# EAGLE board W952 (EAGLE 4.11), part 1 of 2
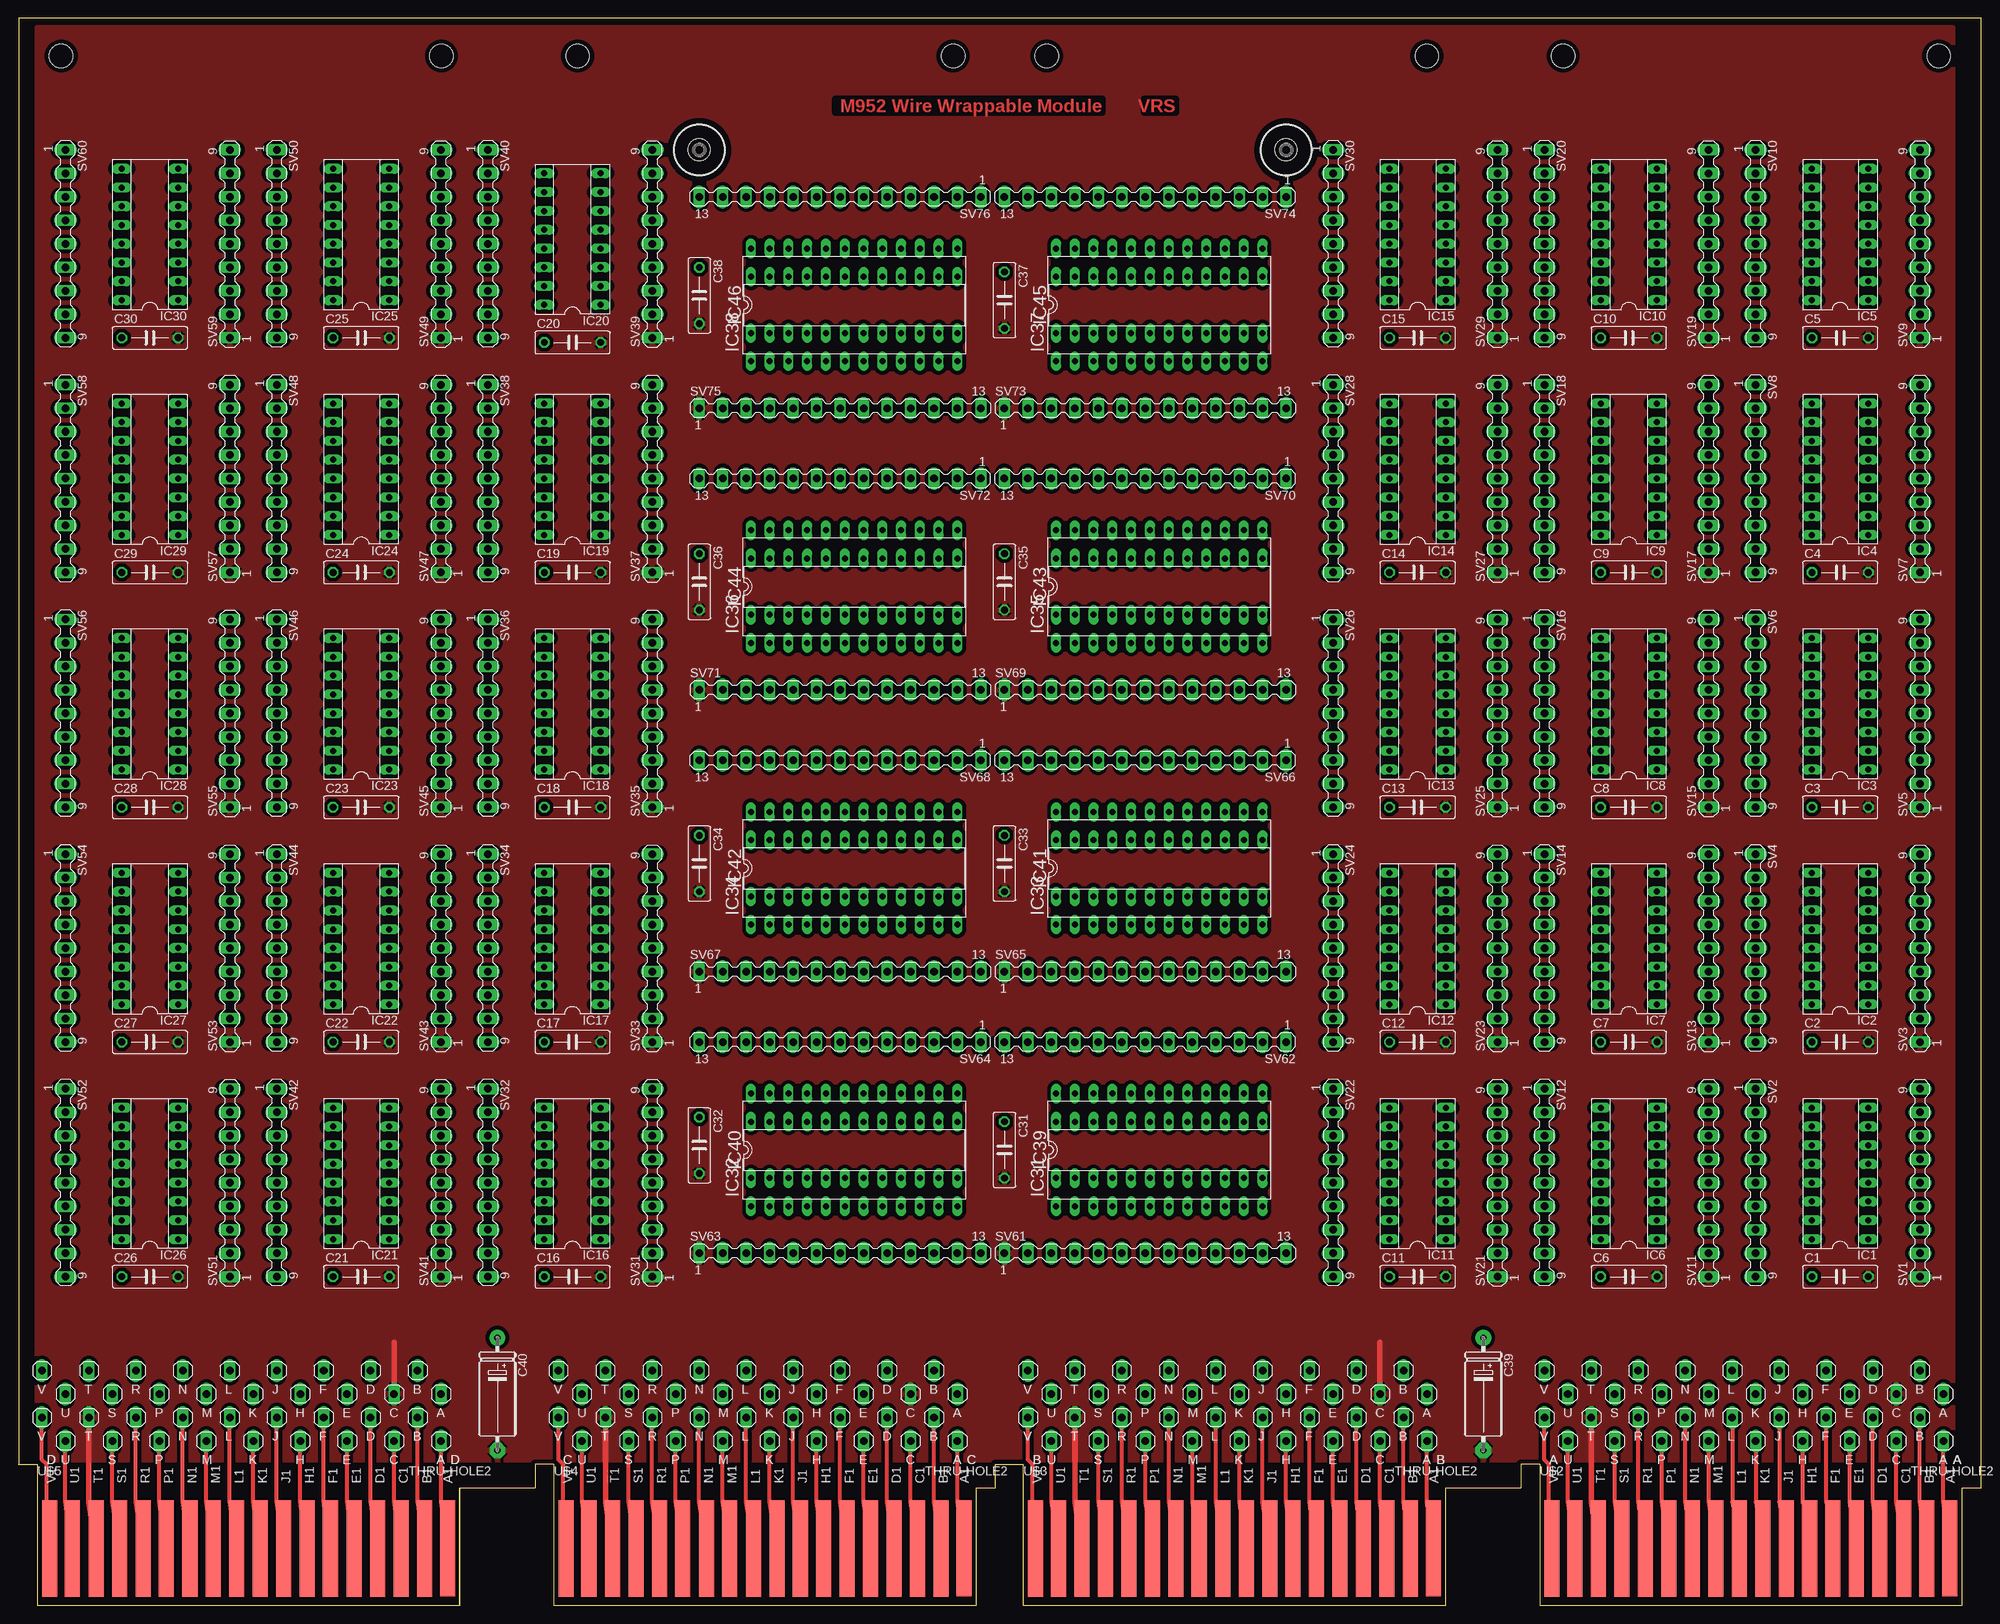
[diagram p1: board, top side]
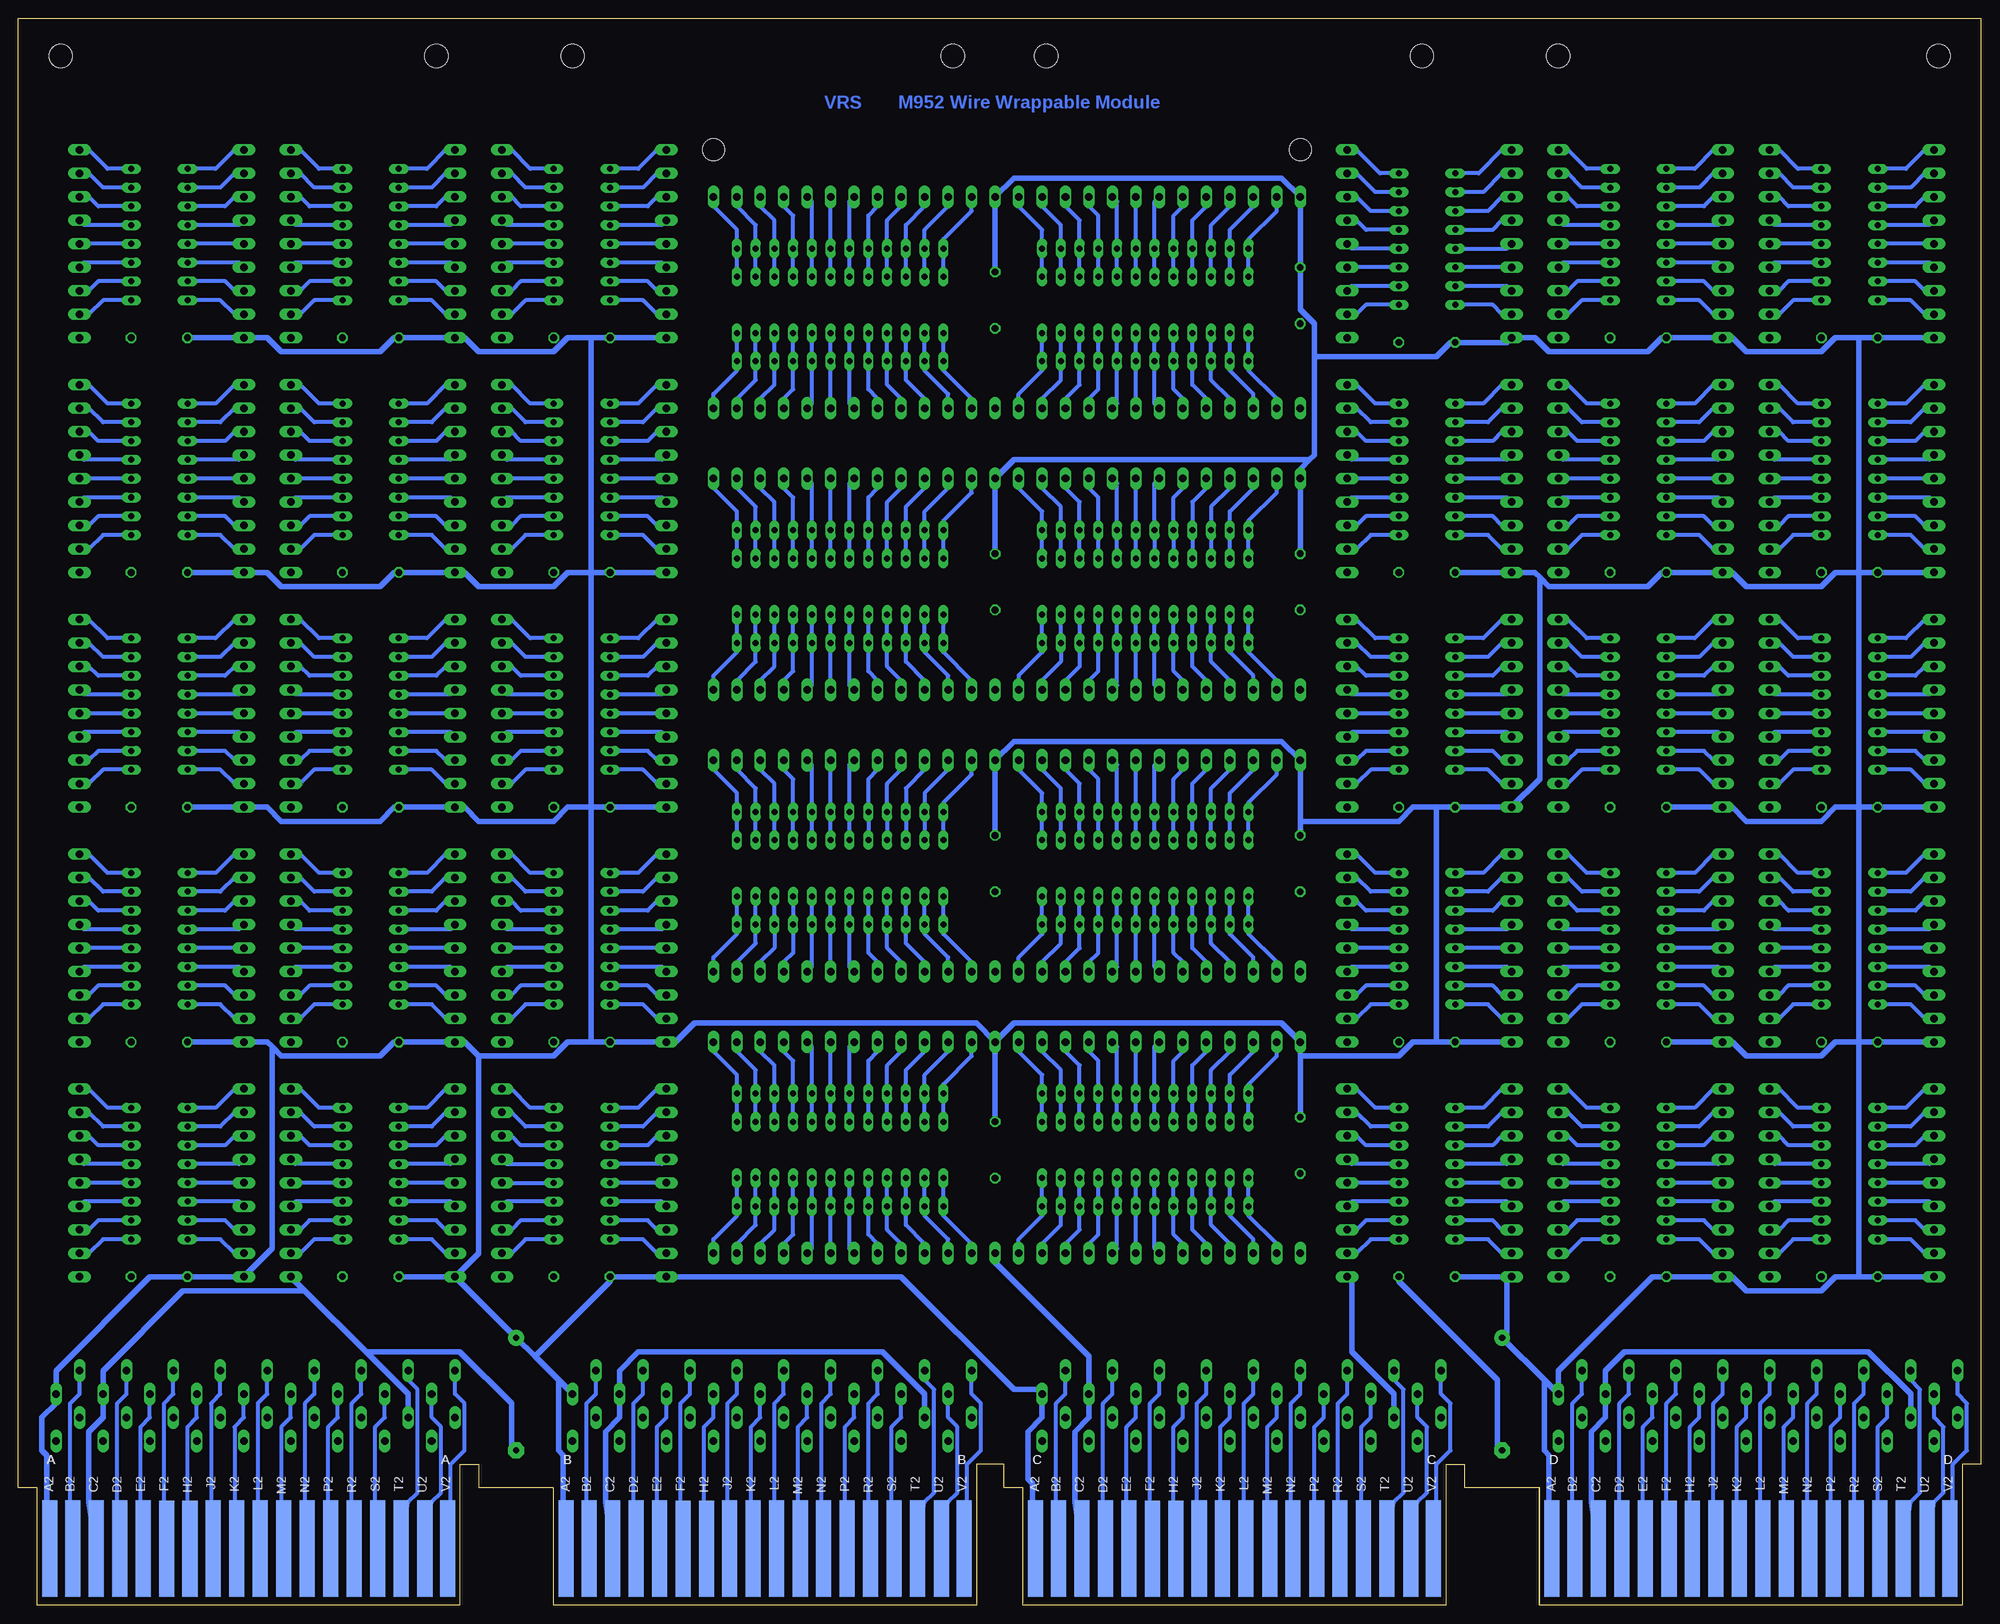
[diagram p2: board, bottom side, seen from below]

Size 265.43 x 214.63 mm. Coordinates in mm from the lower left corner, seen from the top.
Copper layers (1*16): Top 0.035mm / dielectric 1.5mm / Bottom 0.035mm
Design rules "olimex10mil": minimum track width 15mil, minimum drill 24mil, track to track 15mil, track to pad 10mil, pad to pad 10mil, via to via 10mil, smd to smd 10mil, copper to edge 25mil, drill to drill 10mil, minimum pad ring 10mil, minimum via ring 8mil, stop-mask expansion 0mil, vias tented up to drill 0mil, thermal gap 10mil
Net classes: 0 default: width 0.508 mm; 1 supply: width 0.762 mm

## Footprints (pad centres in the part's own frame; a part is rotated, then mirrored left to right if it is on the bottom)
C075-032X103 = drill 0.914 octagon: 1 -3.81,0; 2 3.81,0
E15-5 = drill 0.813 pad 2.159 round: + -7.62,0 | drill 0.813 pad 2.159 octagon: - 7.62,0
SOCKED-16 = drill 0.813 long: 1 -8.89,-3.81; 2 -6.35,-3.81; 3 -3.81,-3.81; 4 -1.27,-3.81; 5 1.27,-3.81; 6 3.81,-3.81; 7 6.35,-3.81; 8 8.89,-3.81; 9 8.89,3.81; 10 6.35,3.81; 11 3.81,3.81; 12 1.27,3.81; 13 -1.27,3.81; 14 -3.81,3.81; 15 -6.35,3.81; 16 -8.89,3.81
DIL24-6 = drill 0.813 long: 1 -13.97,-7.62; 2 -11.43,-7.62; 3 -8.89,-7.62; 4 -6.35,-7.62; 5 -3.81,-7.62; 6 -1.27,-7.62; 7 1.27,-7.62; 8 3.81,-7.62; 9 6.35,-7.62; 10 8.89,-7.62; 11 11.43,-7.62; 12 13.97,-7.62; 13 13.97,7.62; 14 11.43,7.62; 15 8.89,7.62; 16 6.35,7.62; 17 3.81,7.62; 18 1.27,7.62; 19 -1.27,7.62; 20 -3.81,7.62; 21 -6.35,7.62; 22 -8.89,7.62; 23 -11.43,7.62; 24 -13.97,7.62
DIL24-3 = drill 0.813 long: 1 -13.97,-3.81; 2 -11.43,-3.81; 3 -8.89,-3.81; 4 -6.35,-3.81; 5 -3.81,-3.81; 6 -1.27,-3.81; 7 1.27,-3.81; 8 3.81,-3.81; 9 6.35,-3.81; 10 8.89,-3.81; 11 11.43,-3.81; 12 13.97,-3.81; 13 13.97,3.81; 14 11.43,3.81; 15 8.89,3.81; 16 6.35,3.81; 17 3.81,3.81; 18 1.27,3.81; 19 -1.27,3.81; 20 -3.81,3.81; 21 -6.35,3.81; 22 -8.89,3.81; 23 -11.43,3.81; 24 -13.97,3.81
MA09-1 = drill 1.016 long: 1 -12.7,0; 2 -9.525,0; 3 -6.35,0; 4 -3.175,0; 5 0,0; 6 3.175,0; 7 6.35,0; 8 9.525,0; 9 12.7,0
MA13-1 = drill 1.016 long: 1 -19.05,0; 2 -15.875,0; 3 -12.7,0; 4 -9.525,0; 5 -6.35,0; 6 -3.175,0; 7 0,0; 8 3.175,0; 9 6.35,0; 10 9.525,0; 11 12.7,0; 12 15.875,0; 13 19.05,0
EDGE-CON8 = smd 2.032 x 13.017: AA1 261.223,7.709; AB1 258.118,7.684; AC1 254.956,7.684; AD1 251.765,7.684; AE1 248.59,7.693; AF1 245.389,7.668; AH1 242.24,7.668; AJ1 239.09,7.668; AK1 235.915,7.668; AL1 232.74,7.693; AM1 229.54,7.693; AN1 226.39,7.693; AP1 223.19,7.668; AR1 220.04,7.668; AS1 216.865,7.693; AT1 213.69,7.693; AU1 210.49,7.693; AV1 207.404,7.668; BA1 191.373,7.709; BB1 188.268,7.684; BC1 185.106,7.684; BD1 181.915,7.684; BE1 178.74,7.693; BF1 175.539,7.668; BH1 172.39,7.668; BJ1 169.24,7.668; BK1 166.065,7.668; BL1 162.89,7.693; BM1 159.69,7.693; BN1 156.54,7.693; BP1 153.34,7.668; BR1 150.19,7.668; BS1 147.015,7.693; BT1 143.84,7.693; BU1 140.64,7.693; BV1 137.554,7.668; CA1 127.873,7.709; CB1 124.768,7.684; CC1 121.606,7.684; CD1 118.415,7.684; CE1 115.24,7.693; CF1 112.039,7.668; CH1 108.89,7.668; CJ1 105.74,7.668; CK1 102.565,7.668; CL1 99.39,7.693; CM1 96.19,7.693; CN1 93.04,7.693; CP1 89.84,7.668; CR1 86.69,7.668; CS1 83.515,7.693; CT1 80.34,7.693; CU1 77.14,7.693; CV1 74.054,7.668; DA1 58.023,7.709; DB1 54.918,7.684; DC1 51.756,7.684; DD1 48.565,7.684; DE1 45.39,7.693; DF1 42.189,7.668; DH1 39.04,7.668; DJ1 35.89,7.668; DK1 32.715,7.668; DL1 29.54,7.693; DM1 26.34,7.693; DN1 23.19,7.693; DP1 19.99,7.668; DR1 16.84,7.668; DS1 13.665,7.693; DT1 10.49,7.693; DU1 7.29,7.693; DV1 4.204,7.668 | smd 2.032 x 13.017 bottom: AA2 261.223,7.69; AB2 258.102,7.668; AC2 254.94,7.668; AD2 251.765,7.693; AE2 248.59,7.693; AF2 245.389,7.642; AH2 242.24,7.642; AJ2 239.09,7.668; AK2 235.915,7.668; AL2 232.74,7.693; AM2 229.54,7.693; AN2 226.39,7.693; AP2 223.19,7.668; AR2 220.04,7.668; AS2 216.865,7.693; AT2 213.69,7.693; AU2 210.464,7.693; AV2 207.404,7.668; BA2 191.373,7.69; BB2 188.252,7.668; BC2 185.09,7.668; BD2 181.915,7.693; BE2 178.74,7.693; BF2 175.539,7.642; BH2 172.39,7.642; BJ2 169.24,7.668; BK2 166.065,7.668; BL2 162.89,7.693; BM2 159.69,7.693; BN2 156.54,7.693; BP2 153.34,7.668; BR2 150.19,7.668; BS2 147.015,7.693; BT2 143.84,7.693; BU2 140.614,7.693; BV2 137.554,7.668; CA2 127.873,7.69; CB2 124.752,7.668; CC2 121.59,7.668; CD2 118.415,7.693; CE2 115.24,7.693; CF2 112.039,7.642; CH2 108.89,7.642; CJ2 105.74,7.668; CK2 102.565,7.668; CL2 99.39,7.693; CM2 96.19,7.693; CN2 93.04,7.693; CP2 89.84,7.668; CR2 86.69,7.668; CS2 83.515,7.693; CT2 80.34,7.693; CU2 77.114,7.693; CV2 74.054,7.668; DA2 58.023,7.69; DB2 54.902,7.668; DC2 51.74,7.668; DD2 48.565,7.693; DE2 45.39,7.693; DF2 42.189,7.642; DH2 39.04,7.642; DJ2 35.89,7.668; DK2 32.715,7.668; DL2 29.54,7.693; DM2 26.34,7.693; DN2 23.19,7.693; DP2 19.99,7.668; DR2 16.84,7.668; DS2 13.665,7.693; DT2 10.49,7.693; DU2 7.264,7.693; DV2 4.204,7.668
THRU-HOLE2 = drill 1.016 long: A1 28.575,9.525; A2 28.575,3.175; B1 25.4,12.7; B2 25.4,6.35; C1 22.225,9.525; C2 22.225,3.175; D1 19.05,12.7; D2 19.05,6.35; E1 15.875,9.525; E2 15.875,3.175; F1 12.7,12.7; F2 12.7,6.35; H1 9.525,9.525; H2 9.525,3.175; J1 6.35,12.7; J2 6.35,6.35; K1 3.175,9.525; K2 3.175,3.175; L1 0,12.7; L2 0,6.35; M1 -3.175,9.525; M2 -3.175,3.175; N1 -6.35,12.7; N2 -6.35,6.35; P1 -9.525,9.525; P2 -9.525,3.175; R1 -12.7,12.7; R2 -12.7,6.35; S1 -15.875,9.525; S2 -15.875,3.175; T1 -19.05,12.7; T2 -19.05,6.35; U1 -22.225,9.525; U2 -22.225,3.175; V1 -25.4,12.7; V2 -25.4,6.35
OMNIBUS = hole 3.175: 208.915,209.55; 259.715,209.55; 190.5,209.55; 139.065,209.55; 75.616,209.55; 126.416,209.55; 57.201,209.55; 5.766,209.55
DRIL-3 = hole 3: 0,0

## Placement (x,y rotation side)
C1  [C075-032X103]  246.38,44.45 0 top
C2  [C075-032X103]  246.38,76.2 0 top
C3  [C075-032X103]  246.38,107.95 0 top
C4  [C075-032X103]  246.38,139.7 0 top
C5  [C075-032X103]  246.38,171.45 0 top
C6  [C075-032X103]  217.81,44.45 0 top
C7  [C075-032X103]  217.81,76.2 0 top
C8  [C075-032X103]  217.81,107.95 0 top
C9  [C075-032X103]  217.81,139.7 0 top
C10  [C075-032X103]  217.81,171.45 0 top
C11  [C075-032X103]  189.23,44.45 0 top
C12  [C075-032X103]  189.23,76.2 0 top
C13  [C075-032X103]  189.23,107.95 0 top
C14  [C075-032X103]  189.23,139.7 0 top
C15  [C075-032X103]  189.23,171.45 0 top
C16  [C075-032X103]  74.93,44.45 0 top
C17  [C075-032X103]  74.93,76.2 0 top
C18  [C075-032X103]  74.93,107.95 0 top
C19  [C075-032X103]  74.93,139.7 0 top
C20  [C075-032X103]  74.93,170.82 0 top
C21  [C075-032X103]  46.35,44.45 0 top
C22  [C075-032X103]  46.35,76.2 0 top
C23  [C075-032X103]  46.35,107.95 0 top
C24  [C075-032X103]  46.35,139.7 0 top
C25  [C075-032X103]  46.35,171.45 0 top
C26  [C075-032X103]  17.78,44.45 0 top
C27  [C075-032X103]  17.78,76.2 0 top
C28  [C075-032X103]  17.78,107.95 0 top
C29  [C075-032X103]  17.78,139.7 0 top
C30  [C075-032X103]  17.78,171.45 0 top
C31  [C075-032X103]  133.35,61.6 270 top
C32  [C075-032X103]  92.08,62.23 270 top
C33  [C075-032X103]  133.35,100.33 270 top
C34  [C075-032X103]  92.08,100.33 270 top
C35  [C075-032X103]  133.35,138.43 270 top
C36  [C075-032X103]  92.08,138.43 270 top
C37  [C075-032X103]  133.35,176.53 270 top
C38  [C075-032X103]  92.08,177.17 270 top
C39  [E15-5]  198.12,28.58 270 top
C40  [E15-5]  64.77,28.58 270 top
IC1  [SOCKED-16]  246.38,58.42 90 top
IC2  [SOCKED-16]  246.38,90.17 90 top
IC3  [SOCKED-16]  246.38,121.92 90 top
IC4  [SOCKED-16]  246.38,153.67 90 top
IC5  [SOCKED-16]  246.38,185.42 90 top
IC6  [SOCKED-16]  217.81,58.42 90 top
IC7  [SOCKED-16]  217.81,90.17 90 top
IC8  [SOCKED-16]  217.81,121.92 90 top
IC9  [SOCKED-16]  217.81,153.67 90 top
IC10  [SOCKED-16]  217.81,185.42 90 top
IC11  [SOCKED-16]  189.23,58.42 90 top
IC12  [SOCKED-16]  189.23,90.17 90 top
IC13  [SOCKED-16]  189.23,121.92 90 top
IC14  [SOCKED-16]  189.23,153.67 90 top
IC15  [SOCKED-16]  189.23,185.42 90 top
IC16  [SOCKED-16]  74.93,58.42 90 top
IC17  [SOCKED-16]  74.93,90.17 90 top
IC18  [SOCKED-16]  74.93,121.92 90 top
IC19  [SOCKED-16]  74.93,153.67 90 top
IC20  [SOCKED-16]  74.93,184.79 90 top
IC21  [SOCKED-16]  46.35,58.42 90 top
IC22  [SOCKED-16]  46.35,90.17 90 top
IC23  [SOCKED-16]  46.35,121.92 90 top
IC24  [SOCKED-16]  46.35,153.67 90 top
IC25  [SOCKED-16]  46.35,185.42 90 top
IC26  [SOCKED-16]  17.78,58.42 90 top
IC27  [SOCKED-16]  17.78,90.17 90 top
IC28  [SOCKED-16]  17.78,121.92 90 top
IC29  [SOCKED-16]  17.78,153.67 90 top
IC30  [SOCKED-16]  17.78,185.42 90 top
IC31  [DIL24-6]  154.31,61.6 0 top
IC32  [DIL24-6]  113.03,61.6 0 top
IC33  [DIL24-6]  154.31,99.7 0 top
IC34  [DIL24-6]  113.03,99.7 0 top
IC35  [DIL24-6]  154.31,137.8 0 top
IC36  [DIL24-6]  113.03,137.8 0 top
IC37  [DIL24-6]  154.31,175.9 0 top
IC38  [DIL24-6]  113.03,175.9 0 top
IC39  [DIL24-3]  154.31,61.6 0 top
IC40  [DIL24-3]  113.03,61.6 0 top
IC41  [DIL24-3]  154.31,99.7 0 top
IC42  [DIL24-3]  113.03,99.7 0 top
IC43  [DIL24-3]  154.31,137.8 0 top
IC44  [DIL24-3]  113.03,137.8 0 top
IC45  [DIL24-3]  154.31,175.9 0 top
IC46  [DIL24-3]  113.03,175.9 0 top
SV1  MA09-1  [MA09-1]  257.18,57.15 90 top
SV2  MA09-1  [MA09-1]  234.95,57.15 270 top
SV3  MA09-1  [MA09-1]  257.18,88.9 90 top
SV4  MA09-1  [MA09-1]  234.95,88.9 270 top
SV5  MA09-1  [MA09-1]  257.18,120.65 90 top
SV6  MA09-1  [MA09-1]  234.95,120.65 270 top
SV7  MA09-1  [MA09-1]  257.18,152.4 90 top
SV8  MA09-1  [MA09-1]  234.95,152.4 270 top
SV9  MA09-1  [MA09-1]  257.18,184.15 90 top
SV10  MA09-1  [MA09-1]  234.95,184.15 270 top
SV11  MA09-1  [MA09-1]  228.6,57.15 90 top
SV12  MA09-1  [MA09-1]  206.38,57.15 270 top
SV13  MA09-1  [MA09-1]  228.6,88.9 90 top
SV14  MA09-1  [MA09-1]  206.38,88.9 270 top
SV15  MA09-1  [MA09-1]  228.6,120.65 90 top
SV16  MA09-1  [MA09-1]  206.38,120.65 270 top
SV17  MA09-1  [MA09-1]  228.6,152.4 90 top
SV18  MA09-1  [MA09-1]  206.38,152.4 270 top
SV19  MA09-1  [MA09-1]  228.6,184.15 90 top
SV20  MA09-1  [MA09-1]  206.38,184.15 270 top
SV21  MA09-1  [MA09-1]  200.03,57.15 90 top
SV22  MA09-1  [MA09-1]  177.8,57.15 270 top
SV23  MA09-1  [MA09-1]  200.03,88.9 90 top
SV24  MA09-1  [MA09-1]  177.8,88.9 270 top
SV25  MA09-1  [MA09-1]  200.03,120.65 90 top
SV26  MA09-1  [MA09-1]  177.8,120.65 270 top
SV27  MA09-1  [MA09-1]  200.03,152.4 90 top
SV28  MA09-1  [MA09-1]  177.8,152.4 270 top
SV29  MA09-1  [MA09-1]  200.03,184.15 90 top
SV30  MA09-1  [MA09-1]  177.8,184.15 270 top
SV31  MA09-1  [MA09-1]  85.72,57.15 90 top
SV32  MA09-1  [MA09-1]  63.5,57.15 270 top
SV33  MA09-1  [MA09-1]  85.72,88.9 90 top
SV34  MA09-1  [MA09-1]  63.5,88.9 270 top
SV35  MA09-1  [MA09-1]  85.72,120.65 90 top
SV36  MA09-1  [MA09-1]  63.5,120.65 270 top
SV37  MA09-1  [MA09-1]  85.72,152.4 90 top
SV38  MA09-1  [MA09-1]  63.5,152.4 270 top
SV39  MA09-1  [MA09-1]  85.72,184.15 90 top
SV40  MA09-1  [MA09-1]  63.5,184.15 270 top
SV41  MA09-1  [MA09-1]  57.15,57.15 90 top
SV42  MA09-1  [MA09-1]  34.92,57.15 270 top
SV43  MA09-1  [MA09-1]  57.15,88.9 90 top
SV44  MA09-1  [MA09-1]  34.92,88.9 270 top
SV45  MA09-1  [MA09-1]  57.15,120.65 90 top
SV46  MA09-1  [MA09-1]  34.92,120.65 270 top
SV47  MA09-1  [MA09-1]  57.15,152.4 90 top
SV48  MA09-1  [MA09-1]  34.92,152.4 270 top
SV49  MA09-1  [MA09-1]  57.15,184.15 90 top
SV50  MA09-1  [MA09-1]  34.92,184.15 270 top
SV51  MA09-1  [MA09-1]  28.57,57.15 90 top
SV52  MA09-1  [MA09-1]  6.35,57.15 270 top
SV53  MA09-1  [MA09-1]  28.57,88.9 90 top
SV54  MA09-1  [MA09-1]  6.35,88.9 270 top
SV55  MA09-1  [MA09-1]  28.57,120.65 90 top
SV56  MA09-1  [MA09-1]  6.35,120.65 270 top
SV57  MA09-1  [MA09-1]  28.57,152.4 90 top
SV58  MA09-1  [MA09-1]  6.35,152.4 270 top
SV59  MA09-1  [MA09-1]  28.57,184.15 90 top
SV60  MA09-1  [MA09-1]  6.35,184.15 270 top
SV61  MA13-1  [MA13-1]  152.4,47.63 0 top
SV62  MA13-1  [MA13-1]  152.4,76.2 180 top
SV63  MA13-1  [MA13-1]  111.12,47.63 0 top
SV64  MA13-1  [MA13-1]  111.12,76.2 180 top
SV65  MA13-1  [MA13-1]  152.4,85.73 0 top
SV66  MA13-1  [MA13-1]  152.4,114.3 180 top
SV67  MA13-1  [MA13-1]  111.12,85.73 0 top
SV68  MA13-1  [MA13-1]  111.12,114.3 180 top
SV69  MA13-1  [MA13-1]  152.4,123.83 0 top
SV70  MA13-1  [MA13-1]  152.4,152.4 180 top
SV71  MA13-1  [MA13-1]  111.12,123.83 0 top
SV72  MA13-1  [MA13-1]  111.12,152.4 180 top
SV73  MA13-1  [MA13-1]  152.4,161.93 0 top
SV74  MA13-1  [MA13-1]  152.4,190.5 180 top
SV75  MA13-1  [MA13-1]  111.12,161.93 0 top
SV76  MA13-1  [MA13-1]  111.12,190.5 180 top
U$1  [EDGE-CON8]  0,0 0 top
U$2  THRU-HOLE2  [THRU-HOLE2]  231.78,19.05 0 top
U$3  THRU-HOLE2  [THRU-HOLE2]  161.93,19.05 0 top
U$4  THRU-HOLE2  [THRU-HOLE2]  98.42,19.05 0 top
U$5  THRU-HOLE2  [THRU-HOLE2]  28.57,19.05 0 top
U$8  OUTLINE-OMNIBUS  [OMNIBUS]  0,0 0 top
U$9  [DRIL-3]  92.08,196.85 0 top
U$10  [DRIL-3]  171.45,196.85 0 top

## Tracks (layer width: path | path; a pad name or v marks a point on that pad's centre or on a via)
GND
  Top 0.762: U$3.T2 142.88,13.97 U$1.BT1 | U$5.T2 9.53,13.97 U$1.DT1 | U$1.CT1 79.38,13.97 U$4.T2 | U$1.AT1 212.72,13.97 U$2.T2 | U$5.C1 50.8,35.56 | U$3.C1 184.15,35.56
  Bottom 0.762: U$1.BC2 186.06,13.97 186.06,23.5 184.15,25.4 U$3.C1 184.15,31.75 181.61,34.29 148.59,34.29 142.88,28.58 U$3.T2 | U$1.DC2 52.7,13.97 52.7,23.5 50.8,25.4 U$5.C1 50.8,31.75 48.26,34.29 15.24,34.29 9.53,28.58 U$5.T2 | U$1.AC2 255.91,13.97 255.91,23.5 254,25.4 U$2.C1 254,31.75 243.21,42.55 226.69,42.55 | U$1.CC2 122.56,13.97 122.56,23.5 120.65,25.4 U$4.C1 120.65,33.66 133.35,46.36 SV61.1 | U$4.T2 79.38,28.58 85.09,34.29 85.09,43.82 SV31.1 | 226.69,42.55 218.44,34.29 | 218.44,34.29 212.72,28.58 U$2.T2 | 226.69,42.55 SV11.1 | C40.- 65.41,21.59 65.41,30.48 78.74,43.82 C16.2 | 218.44,34.29 205.74,34.29 198.75,27.31 198.75,21.59 C39.-
  pour Top (isolate 0.508): 2.54,19.69 261.62,19.69 261.62,213.36 2.54,213.36
N$1
  Top 0.508: U$2.K2 234.95,13.97 U$1.AK1
N$2
  Top 0.508: U$2.J2 238.12,13.97 U$1.AJ1
N$3
  Top 0.508: U$2.H2 241.3,13.97 U$1.AH1
N$4
  Top 0.508: U$2.L2 231.78,13.97 U$1.AL1
N$5
  Top 0.508: U$2.M2 228.6,13.97 U$1.AM1
N$6
  Top 0.508: U$2.N2 225.43,13.97 U$1.AN1
N$7
  Top 0.508: U$2.P2 222.25,13.97 U$1.AP1
N$8
  Top 0.508: U$2.F2 244.47,13.97 U$1.AF1
N$9
  Top 0.508: U$2.E2 247.65,13.97 U$1.AE1
N$10
  Top 0.508: U$2.D2 250.82,13.97 U$1.AD1
N$11
  Top 0.508: U$2.C2 254,13.97 U$1.AC1
N$12
  Top 0.508: U$2.R2 219.07,13.97 U$1.AR1
N$13
  Top 0.508: U$2.S2 215.9,13.97 U$1.AS1
N$14
  Top 0.508: U$2.B2 257.18,13.97 U$1.AB1
N$15
  Top 0.508: U$2.A2 260.35,13.97 U$1.AA1
N$16
  Top 0.508: U$2.U2 209.55,13.97 U$1.AU1
N$17
  Top 0.508: U$2.V2 206.38,19.69 207.01,19.05 207.01,13.97 U$1.AV1
N$18
  Bottom 0.508: U$2.V1 206.38,28.58 205.1,27.31 205.1,20.96 207.01,19.05 207.01,13.97 U$1.AV2
N$19
  Bottom 0.508: U$2.U1 209.55,25.4 208.28,24.13 208.28,15.24 209.55,13.97 U$1.AU2
N$20
  Bottom 0.508: U$2.T1 212.72,30.48 211.46,29.21 211.46,15.24 212.72,13.97 U$1.AT2
N$21
  Bottom 0.508: U$2.S1 215.9,25.4 217.17,24.13 217.17,13.97 U$1.AS2
N$22
  Bottom 0.508: U$2.R1 219.07,28.58 220.34,27.31 220.34,13.97 U$1.AR2
N$23
  Bottom 0.508: U$2.P1 222.25,25.4 223.52,24.13 223.52,13.97 U$1.AP2
N$24
  Bottom 0.508: U$2.N1 225.43,28.58 226.69,27.31 226.69,13.97 U$1.AN2
N$25
  Bottom 0.508: U$2.M1 228.6,25.4 229.87,24.13 229.87,13.97 U$1.AM2
N$26
  Bottom 0.508: U$2.L1 231.78,28.58 233.04,27.31 233.04,13.97 U$1.AL2
N$27
  Bottom 0.508: U$2.K1 234.95,25.4 236.22,24.13 236.22,13.97 U$1.AK2
N$28
  Bottom 0.508: U$2.J1 238.12,28.58 239.4,27.31 239.4,13.97 U$1.AJ2
N$29
  Bottom 0.508: U$2.H1 241.3,25.4 242.57,24.13 242.57,13.97 U$1.AH2
N$30
  Bottom 0.508: U$2.F1 244.47,28.58 245.75,27.31 245.75,13.97 U$1.AF2
N$31
  Bottom 0.508: U$2.E1 247.65,25.4 248.92,24.13 248.92,13.97 U$1.AE2
N$32
  Bottom 0.508: U$2.D1 250.82,28.58 252.09,27.31 252.09,13.97 U$1.AD2
N$33
  Bottom 0.508: U$2.B1 257.18,28.58 258.44,27.31 258.44,13.97 U$1.AB2
N$34
  Top 0.508: U$3.V2 136.53,19.69 137.16,19.05 137.16,13.97 U$1.BV1
N$35
  Top 0.508: U$3.U2 139.7,13.97 U$1.BU1
N$36
  Top 0.508: U$3.S2 146.05,13.97 U$1.BS1
N$37
  Top 0.508: U$3.R2 149.22,13.97 U$1.BR1
N$38
  Top 0.508: U$3.P2 152.4,13.97 U$1.BP1
N$39
  Top 0.508: U$3.N2 155.57,13.97 U$1.BN1
N$40
  Top 0.508: U$3.M2 158.75,13.97 U$1.BM1
N$41
  Top 0.508: U$3.L2 161.93,13.97 U$1.BL1
N$42
  Top 0.508: U$3.K2 165.1,13.97 U$1.BK1
N$43
  Top 0.508: U$3.J2 168.28,13.97 U$1.BJ1
N$44
  Top 0.508: U$3.H2 171.45,13.97 U$1.BH1
N$45
  Top 0.508: U$3.F2 174.62,13.97 U$1.BF1
N$46
  Top 0.508: U$3.E2 177.8,13.97 U$1.BE1
N$47
  Top 0.508: U$3.D2 180.97,13.97 U$1.BD1
N$48
  Top 0.508: U$3.C2 184.15,13.97 U$1.BC1
N$49
  Top 0.508: U$3.B2 187.32,13.97 U$1.BB1
N$50
  Top 0.508: U$3.A2 190.5,13.97 U$1.BA1
N$51
  Bottom 0.508: U$3.V1 136.53,28.58 135.25,27.31 135.25,20.96 137.16,19.05 137.16,13.97 U$1.BV2
N$52
  Bottom 0.508: U$3.U1 139.7,25.4 138.43,24.13 138.43,15.24 139.7,13.97 U$1.BU2
N$53
  Bottom 0.508: U$3.T1 142.88,30.48 141.6,29.21 141.6,15.24 142.88,13.97 U$1.BT2
N$54
  Bottom 0.508: U$3.S1 146.05,25.4 147.32,24.13 147.32,13.97 U$1.BS2
N$55
  Bottom 0.508: U$3.R1 149.22,28.58 150.5,27.31 150.5,13.97 U$1.BR2
N$56
  Bottom 0.508: U$3.P1 152.4,25.4 153.67,24.13 153.67,13.97 U$1.BP2
N$57
  Bottom 0.508: U$3.N1 155.57,28.58 156.84,27.31 156.84,13.97 U$1.BN2
N$58
  Bottom 0.508: U$3.M1 158.75,25.4 160.02,24.13 160.02,13.97 U$1.BM2
N$59
  Bottom 0.508: U$3.L1 161.93,28.58 163.19,27.31 163.19,13.97 U$1.BL2
N$60
  Bottom 0.508: U$3.K1 165.1,25.4 166.37,24.13 166.37,13.97 U$1.BK2
N$61
  Bottom 0.508: U$3.J1 168.28,28.58 169.54,27.31 169.54,13.97 U$1.BJ2
N$62
  Bottom 0.508: U$3.H1 171.45,25.4 172.72,24.13 172.72,13.97 U$1.BH2
N$63
  Bottom 0.508: U$3.F1 174.62,28.58 175.9,27.31 175.9,13.97 U$1.BF2
N$64
  Bottom 0.508: U$3.E1 177.8,25.4 179.07,24.13 179.07,13.97 U$1.BE2
N$65
  Bottom 0.508: U$3.D1 180.97,28.58 182.25,27.31 182.25,13.97 U$1.BD2
N$66
  Bottom 0.508: U$3.B1 187.32,28.58 188.59,27.31 188.59,13.97 U$1.BB2
N$67
  Top 0.508: U$4.V2 73.03,19.69 73.66,19.05 73.66,13.97 U$1.CV1
N$68
  Top 0.508: U$4.U2 76.2,13.97 U$1.CU1
N$69
  Top 0.508: U$4.S2 82.55,13.97 U$1.CS1
N$70
  Top 0.508: U$4.R2 85.72,13.97 U$1.CR1
N$71
  Top 0.508: U$4.P2 88.9,13.97 U$1.CP1
N$72
  Top 0.508: U$4.N2 92.08,13.97 U$1.CN1
N$73
  Top 0.508: U$4.M2 95.25,13.97 U$1.CM1
N$74
  Top 0.508: U$4.L2 98.42,13.97 U$1.CL1
N$75
  Top 0.508: U$4.K2 101.6,13.97 U$1.CK1
N$76
  Top 0.508: U$4.J2 104.78,13.97 U$1.CJ1
N$77
  Top 0.508: U$4.H2 107.95,13.97 U$1.CH1
N$78
  Top 0.508: U$4.F2 111.12,13.97 U$1.CF1
N$79
  Top 0.508: U$4.E2 114.3,13.97 U$1.CE1
N$80
  Top 0.508: U$4.D2 117.47,13.97 U$1.CD1
N$81
  Top 0.508: U$4.C2 120.65,13.97 U$1.CC1
N$82
  Top 0.508: U$4.B2 123.83,13.97 U$1.CB1
N$83
  Top 0.508: U$4.A2 127,13.97 U$1.CA1
N$84
  Bottom 0.508: U$4.V1 73.03,28.58 71.75,27.31 71.75,20.96 73.66,19.05 73.66,13.97 U$1.CV2
N$85
  Bottom 0.508: U$4.U1 76.2,25.4 74.93,24.13 74.93,15.24 76.2,13.97 U$1.CU2
N$86
  Bottom 0.508: U$4.T1 79.38,30.48 78.11,29.21 78.11,15.24 79.38,13.97 U$1.CT2
N$87
  Bottom 0.508: U$4.S1 82.55,25.4 83.82,24.13 83.82,13.97 U$1.CS2
N$88
  Bottom 0.508: U$4.R1 85.72,28.58 87,27.31 87,13.97 U$1.CR2
N$89
  Bottom 0.508: U$4.P1 88.9,25.4 90.17,24.13 90.17,13.97 U$1.CP2
N$90
  Bottom 0.508: U$4.N1 92.08,28.58 93.34,27.31 93.34,13.97 U$1.CN2
N$91
  Bottom 0.508: U$4.M1 95.25,25.4 96.52,24.13 96.52,13.97 U$1.CM2
N$92
  Bottom 0.508: U$4.L1 98.42,28.58 99.69,27.31 99.69,13.97 U$1.CL2
N$93
  Bottom 0.508: U$4.K1 101.6,25.4 102.87,24.13 102.87,13.97 U$1.CK2
N$94
  Bottom 0.508: U$4.J1 104.78,28.58 106.05,27.31 106.05,13.97 U$1.CJ2
N$95
  Bottom 0.508: U$4.H1 107.95,25.4 109.22,24.13 109.22,13.97 U$1.CH2
N$96
  Bottom 0.508: U$4.F1 111.12,28.58 112.39,27.31 112.39,13.97 U$1.CF2
N$97
  Bottom 0.508: U$4.E1 114.3,25.4 115.57,24.13 115.57,13.97 U$1.CE2
N$98
  Bottom 0.508: U$4.D1 117.47,28.58 118.75,27.31 118.75,13.97 U$1.CD2
N$99
  Bottom 0.508: U$4.B1 123.83,28.58 125.09,27.31 125.09,13.97 U$1.CB2
N$100
  Top 0.508: U$5.V2 3.17,19.69 3.81,19.05 3.81,13.97 U$1.DV1
N$101
  Top 0.508: U$5.U2 6.35,13.97 U$1.DU1
N$102
  Top 0.508: U$5.S2 12.7,13.97 U$1.DS1
N$103
  Top 0.508: U$5.R2 15.88,13.97 U$1.DR1
N$104
  Top 0.508: U$5.P2 19.05,13.97 U$1.DP1
N$105
  Top 0.508: U$5.N2 22.23,13.97 U$1.DN1
N$106
  Top 0.508: U$5.M2 25.4,13.97 U$1.DM1
N$107
  Top 0.508: U$5.L2 28.57,13.97 U$1.DL1
N$108
  Top 0.508: U$5.K2 31.75,13.97 U$1.DK1
N$109
  Top 0.508: U$5.J2 34.92,13.97 U$1.DJ1
N$110
  Top 0.508: U$5.H2 38.1,13.97 U$1.DH1
N$111
  Top 0.508: U$5.F2 41.27,13.97 U$1.DF1
N$112
  Top 0.508: U$5.E2 44.45,13.97 U$1.DE1
N$113
  Top 0.508: U$5.D2 47.62,13.97 U$1.DD1
N$114
  Top 0.508: U$5.C2 50.8,13.97 U$1.DC1
N$115
  Top 0.508: U$5.B2 53.98,13.97 U$1.DB1
N$116
  Top 0.508: U$5.A2 57.15,13.97 U$1.DA1
N$117
  Bottom 0.508: U$5.V1 3.17,28.58 1.91,27.31 1.91,20.96 3.81,19.05 3.81,13.97 U$1.DV2
N$118
  Bottom 0.508: U$5.U1 6.35,25.4 5.08,24.13 5.08,15.24 6.35,13.97 U$1.DU2
N$119
  Bottom 0.508: U$5.T1 9.53,30.48 8.26,29.21 8.26,15.24 9.53,13.97 U$1.DT2
N$120
  Bottom 0.508: U$5.S1 12.7,25.4 13.97,24.13 13.97,13.97 U$1.DS2
N$121
  Bottom 0.508: U$5.R1 15.88,28.58 17.14,27.31 17.14,13.97 U$1.DR2
N$122
  Bottom 0.508: U$5.P1 19.05,25.4 20.32,24.13 20.32,13.97 U$1.DP2
N$123
  Bottom 0.508: U$5.N1 22.23,28.58 23.5,27.31 23.5,13.97 U$1.DN2
N$124
  Bottom 0.508: U$5.M1 25.4,25.4 26.67,24.13 26.67,13.97 U$1.DM2
N$125
  Bottom 0.508: U$5.L1 28.57,28.58 29.84,27.31 29.84,13.97 U$1.DL2
N$126
  Bottom 0.508: U$5.K1 31.75,25.4 33.02,24.13 33.02,13.97 U$1.DK2
N$127
  Bottom 0.508: U$5.J1 34.92,28.58 36.2,27.31 36.2,13.97 U$1.DJ2
N$128
  Bottom 0.508: U$5.H1 38.1,25.4 39.37,24.13 39.37,13.97 U$1.DH2
N$129
  Bottom 0.508: U$5.F1 41.27,28.58 42.55,27.31 42.55,13.97 U$1.DF2
N$130
  Bottom 0.508: U$5.E1 44.45,25.4 45.72,24.13 45.72,13.97 U$1.DE2
N$131
  Bottom 0.508: U$5.D1 47.62,28.58 48.9,27.31 48.9,13.97 U$1.DD2
N$132
  Bottom 0.508: U$5.B1 53.98,28.58 55.24,27.31 55.24,13.97 U$1.DB2
N$133
  Bottom 0.508: IC1.1 254,49.53 255.91,47.63 SV1.2
N$134
  Bottom 0.508: IC1.2 254.63,52.07 255.91,50.8 SV1.3
N$135
  Bottom 0.508: IC1.3 256.54,54.61 SV1.4
N$136
  Bottom 0.508: IC1.4 SV1.5
N$137
  Bottom 0.508: IC1.5 256.54,59.69 SV1.6
N$138
  Bottom 0.508: IC1.6 254.63,62.23 255.91,63.5 SV1.7
N$139
  Bottom 0.508: IC1.7 254,64.77 255.91,66.68 SV1.8
N$140
  Bottom 0.508: IC1.8 253.37,67.31 255.91,69.85 SV1.9
N$141
  Bottom 0.508: IC1.9 238.76,67.31 236.22,69.85 SV2.1
N$142
  Bottom 0.508: IC1.10 238.12,64.77 236.22,66.68 SV2.2
N$143
  Bottom 0.508: IC1.11 237.49,62.23 236.22,63.5 SV2.3
N$144
  Bottom 0.508: IC1.12 235.59,59.69 SV2.4
N$145
  Bottom 0.508: SV2.5 IC1.13
N$146
  Bottom 0.508: IC1.14 235.59,54.61 SV2.6
N$147
  Bottom 0.508: IC1.15 237.49,52.07 236.22,50.8 SV2.7
N$148
  Bottom 0.508: IC1.16 238.12,49.53 236.22,47.63 SV2.8
N$151
  Bottom 0.508: IC2.1 254,81.28 255.91,79.38 SV3.2
N$152
  Bottom 0.508: IC2.2 254.63,83.82 255.91,82.55 SV3.3
N$153
  Bottom 0.508: IC2.3 256.54,86.36 SV3.4
N$154
  Bottom 0.508: IC2.4 SV3.5
N$155
  Bottom 0.508: IC2.5 256.54,91.44 SV3.6
N$156
  Bottom 0.508: IC2.6 254.63,93.98 255.91,95.25 SV3.7
N$157
  Bottom 0.508: IC2.7 254,96.52 255.91,98.43 SV3.8
N$158
  Bottom 0.508: IC2.8 253.37,99.06 255.91,101.6 SV3.9
N$159
  Bottom 0.508: IC2.9 238.76,99.06 236.22,101.6 SV4.1
N$160
  Bottom 0.508: IC2.10 238.12,96.52 236.22,98.43 SV4.2
N$161
  Bottom 0.508: IC2.11 237.49,93.98 236.22,95.25 SV4.3
N$162
  Bottom 0.508: IC2.12 235.59,91.44 SV4.4
N$163
  Bottom 0.508: SV4.5 IC2.13
N$164
  Bottom 0.508: IC2.14 235.59,86.36 SV4.6
N$165
  Bottom 0.508: IC2.15 237.49,83.82 236.22,82.55 SV4.7
N$166
  Bottom 0.508: IC2.16 238.12,81.28 236.22,79.38 SV4.8
N$169
  Bottom 0.508: IC3.1 254,113.03 255.91,111.13 SV5.2
N$170
  Bottom 0.508: IC3.2 254.63,115.57 255.91,114.3 SV5.3
N$171
  Bottom 0.508: IC3.3 256.54,118.11 SV5.4
N$172
  Bottom 0.508: IC3.4 SV5.5
N$173
  Bottom 0.508: IC3.5 256.54,123.19 SV5.6
N$174
  Bottom 0.508: IC3.6 254.63,125.73 255.91,127 SV5.7
N$175
  Bottom 0.508: IC3.7 254,128.27 255.91,130.18 SV5.8
N$176
  Bottom 0.508: IC3.8 253.37,130.81 255.91,133.35 SV5.9
N$177
  Bottom 0.508: IC3.9 238.76,130.81 236.22,133.35 SV6.1
N$178
  Bottom 0.508: IC3.10 238.12,128.27 236.22,130.18 SV6.2
N$179
  Bottom 0.508: IC3.11 237.49,125.73 236.22,127 SV6.3
N$180
  Bottom 0.508: IC3.12 235.59,123.19 SV6.4
N$181
  Bottom 0.508: SV6.5 IC3.13
N$182
  Bottom 0.508: IC3.14 235.59,118.11 SV6.6
N$183
  Bottom 0.508: IC3.15 237.49,115.57 236.22,114.3 SV6.7
N$184
  Bottom 0.508: IC3.16 238.12,113.03 236.22,111.13 SV6.8
N$187
  Bottom 0.508: IC4.1 254,144.78 255.91,142.88 SV7.2
N$188
  Bottom 0.508: IC4.2 254.63,147.32 255.91,146.05 SV7.3
N$189
  Bottom 0.508: IC4.3 256.54,149.86 SV7.4
N$190
  Bottom 0.508: IC4.4 SV7.5
N$191
  Bottom 0.508: IC4.5 256.54,154.94 SV7.6
N$192
  Bottom 0.508: IC4.6 254.63,157.48 255.91,158.75 SV7.7
N$193
  Bottom 0.508: IC4.7 254,160.02 255.91,161.93 SV7.8
N$194
  Bottom 0.508: IC4.8 253.37,162.56 255.91,165.1 SV7.9
N$195
  Bottom 0.508: IC4.9 238.76,162.56 236.22,165.1 SV8.1
N$196
  Bottom 0.508: IC4.10 238.12,160.02 236.22,161.93 SV8.2
N$197
  Bottom 0.508: IC4.11 237.49,157.48 236.22,158.75 SV8.3
N$198
  Bottom 0.508: IC4.12 235.59,154.94 SV8.4
N$199
  Bottom 0.508: SV8.5 IC4.13
N$200
  Bottom 0.508: IC4.14 235.59,149.86 SV8.6
N$201
  Bottom 0.508: IC4.15 237.49,147.32 236.22,146.05 SV8.7
N$202
  Bottom 0.508: IC4.16 238.12,144.78 236.22,142.88 SV8.8
N$205
  Bottom 0.508: IC5.1 254,176.53 255.91,174.63 SV9.2
N$206
  Bottom 0.508: IC5.2 254.63,179.07 255.91,177.8 SV9.3
N$207
  Bottom 0.508: IC5.3 256.54,181.61 SV9.4
N$208
  Bottom 0.508: IC5.4 SV9.5
N$209
  Bottom 0.508: IC5.5 256.54,186.69 SV9.6
N$210
  Bottom 0.508: IC5.6 254.63,189.23 255.91,190.5 SV9.7
N$211
  Bottom 0.508: IC5.7 254,191.77 255.91,193.68 SV9.8
N$212
  Bottom 0.508: IC5.8 253.37,194.31 255.91,196.85 SV9.9
N$213
  Bottom 0.508: IC5.9 238.76,194.31 236.22,196.85 SV10.1
N$214
  Bottom 0.508: IC5.10 238.12,191.77 236.22,193.68 SV10.2
N$215
  Bottom 0.508: IC5.11 237.49,189.23 236.22,190.5 SV10.3
N$216
  Bottom 0.508: IC5.12 235.59,186.69 SV10.4
N$217
  Bottom 0.508: SV10.5 IC5.13
N$218
  Bottom 0.508: IC5.14 235.59,181.61 SV10.6
N$219
  Bottom 0.508: IC5.15 237.49,179.07 236.22,177.8 SV10.7
N$220
  Bottom 0.508: IC5.16 238.12,176.53 236.22,174.63 SV10.8
N$223
  Bottom 0.508: IC6.1 225.43,49.53 227.33,47.63 SV11.2
N$224
  Bottom 0.508: IC6.2 226.06,52.07 227.33,50.8 SV11.3
N$225
  Bottom 0.508: IC6.3 227.97,54.61 SV11.4
N$226
  Bottom 0.508: IC6.4 SV11.5
N$227
  Bottom 0.508: IC6.5 227.97,59.69 SV11.6
N$228
  Bottom 0.508: IC6.6 226.06,62.23 227.33,63.5 SV11.7
N$229
  Bottom 0.508: IC6.7 225.43,64.77 227.33,66.68 SV11.8
N$230
  Bottom 0.508: IC6.8 224.79,67.31 227.33,69.85 SV11.9
N$231
  Bottom 0.508: IC6.9 210.19,67.31 207.65,69.85 SV12.1
N$232
  Bottom 0.508: IC6.10 209.55,64.77 207.65,66.68 SV12.2
N$233
  Bottom 0.508: IC6.11 208.91,62.23 207.65,63.5 SV12.3
N$234
  Bottom 0.508: IC6.12 207.01,59.69 SV12.4
N$235
  Bottom 0.508: SV12.5 IC6.13
N$236
  Bottom 0.508: IC6.14 207.01,54.61 SV12.6
N$237
  Bottom 0.508: IC6.15 208.91,52.07 207.65,50.8 SV12.7
N$238
  Bottom 0.508: IC6.16 209.55,49.53 207.65,47.63 SV12.8
N$241
  Bottom 0.508: IC7.1 225.43,81.28 227.33,79.38 SV13.2
N$242
  Bottom 0.508: IC7.2 226.06,83.82 227.33,82.55 SV13.3
N$243
  Bottom 0.508: IC7.3 227.97,86.36 SV13.4
N$244
  Bottom 0.508: IC7.4 SV13.5
N$245
  Bottom 0.508: IC7.5 227.97,91.44 SV13.6
N$246
  Bottom 0.508: IC7.6 226.06,93.98 227.33,95.25 SV13.7
N$247
  Bottom 0.508: IC7.7 225.43,96.52 227.33,98.43 SV13.8
N$248
  Bottom 0.508: IC7.8 224.79,99.06 227.33,101.6 SV13.9
N$249
  Bottom 0.508: IC7.9 210.19,99.06 207.65,101.6 SV14.1
N$250
  Bottom 0.508: IC7.10 209.55,96.52 207.65,98.43 SV14.2
N$251
  Bottom 0.508: IC7.11 208.91,93.98 207.65,95.25 SV14.3
N$252
  Bottom 0.508: IC7.12 207.01,91.44 SV14.4
N$253
  Bottom 0.508: SV14.5 IC7.13
N$254
  Bottom 0.508: IC7.14 207.01,86.36 SV14.6
N$255
  Bottom 0.508: IC7.15 208.91,83.82 207.65,82.55 SV14.7
N$256
  Bottom 0.508: IC7.16 209.55,81.28 207.65,79.38 SV14.8
N$259
  Bottom 0.508: IC8.1 225.43,113.03 227.33,111.13 SV15.2
N$260
  Bottom 0.508: IC8.2 226.06,115.57 227.33,114.3 SV15.3
N$261
  Bottom 0.508: IC8.3 227.97,118.11 SV15.4
N$262
  Bottom 0.508: IC8.4 SV15.5
N$263
  Bottom 0.508: IC8.5 227.97,123.19 SV15.6
N$264
  Bottom 0.508: IC8.6 226.06,125.73 227.33,127 SV15.7
N$265
  Bottom 0.508: IC8.7 225.43,128.27 227.33,130.18 SV15.8
N$266
  Bottom 0.508: IC8.8 224.79,130.81 227.33,133.35 SV15.9
N$267
  Bottom 0.508: IC8.9 210.19,130.81 207.65,133.35 SV16.1
N$268
  Bottom 0.508: IC8.10 209.55,128.27 207.65,130.18 SV16.2
N$269
  Bottom 0.508: IC8.11 208.91,125.73 207.65,127 SV16.3
N$270
  Bottom 0.508: IC8.12 207.01,123.19 SV16.4
N$271
  Bottom 0.508: SV16.5 IC8.13
N$272
  Bottom 0.508: IC8.14 207.01,118.11 SV16.6
N$273
  Bottom 0.508: IC8.15 208.91,115.57 207.65,114.3 SV16.7
N$274
  Bottom 0.508: IC8.16 209.55,113.03 207.65,111.13 SV16.8
N$277
  Bottom 0.508: IC9.1 225.43,144.78 227.33,142.88 SV17.2
N$278
  Bottom 0.508: IC9.2 226.06,147.32 227.33,146.05 SV17.3
N$279
  Bottom 0.508: IC9.3 227.97,149.86 SV17.4
N$280
  Bottom 0.508: IC9.4 SV17.5
N$281
  Bottom 0.508: IC9.5 227.97,154.94 SV17.6
N$282
  Bottom 0.508: IC9.6 226.06,157.48 227.33,158.75 SV17.7
N$283
  Bottom 0.508: IC9.7 225.43,160.02 227.33,161.93 SV17.8
N$284
  Bottom 0.508: IC9.8 224.79,162.56 227.33,165.1 SV17.9
N$285
  Bottom 0.508: IC9.9 210.19,162.56 207.65,165.1 SV18.1
N$286
  Bottom 0.508: IC9.10 209.55,160.02 207.65,161.93 SV18.2
N$287
  Bottom 0.508: IC9.11 208.91,157.48 207.65,158.75 SV18.3
N$288
  Bottom 0.508: IC9.12 207.01,154.94 SV18.4
N$289
  Bottom 0.508: SV18.5 IC9.13
N$290
  Bottom 0.508: IC9.14 207.01,149.86 SV18.6
N$291
  Bottom 0.508: IC9.15 208.91,147.32 207.65,146.05 SV18.7
N$292
  Bottom 0.508: IC9.16 209.55,144.78 207.65,142.88 SV18.8
N$295
  Bottom 0.508: IC10.1 225.43,176.53 227.33,174.63 SV19.2
N$296
  Bottom 0.508: IC10.2 226.06,179.07 227.33,177.8 SV19.3
N$297
  Bottom 0.508: IC10.3 227.97,181.61 SV19.4
N$298
  Bottom 0.508: IC10.4 SV19.5
N$299
  Bottom 0.508: IC10.5 227.97,186.69 SV19.6
N$300
  Bottom 0.508: IC10.6 226.06,189.23 227.33,190.5 SV19.7
N$301
  Bottom 0.508: IC10.7 225.43,191.77 227.33,193.68 SV19.8
N$302
  Bottom 0.508: IC10.8 224.79,194.31 227.33,196.85 SV19.9
N$303
  Bottom 0.508: IC10.9 210.19,194.31 207.65,196.85 SV20.1
N$304
  Bottom 0.508: IC10.10 209.55,191.77 207.65,193.68 SV20.2
N$305
  Bottom 0.508: IC10.11 208.91,189.23 207.65,190.5 SV20.3
N$306
  Bottom 0.508: IC10.12 207.01,186.69 SV20.4
N$307
  Bottom 0.508: SV20.5 IC10.13
N$308
  Bottom 0.508: IC10.14 207.01,181.61 SV20.6
N$309
  Bottom 0.508: IC10.15 208.91,179.07 207.65,177.8 SV20.7
N$310
  Bottom 0.508: IC10.16 209.55,176.53 207.65,174.63 SV20.8
N$313
  Bottom 0.508: IC11.1 196.85,49.53 198.75,47.63 SV21.2
N$314
  Bottom 0.508: IC11.2 197.49,52.07 198.75,50.8 SV21.3
N$315
  Bottom 0.508: IC11.3 199.39,54.61 SV21.4
N$316
  Bottom 0.508: SV21.5 IC11.4
N$317
  Bottom 0.508: IC11.5 199.39,59.69 SV21.6
N$318
  Bottom 0.508: IC11.6 197.49,62.23 198.75,63.5 SV21.7
N$319
  Bottom 0.508: IC11.7 196.85,64.77 198.75,66.68 SV21.8
N$320
  Bottom 0.508: IC11.8 196.22,67.31 198.75,69.85 SV21.9
N$321
  Bottom 0.508: IC11.9 181.61,67.31 179.07,69.85 SV22.1
N$322
  Bottom 0.508: IC11.10 180.97,64.77 179.07,66.68 SV22.2
N$323
  Bottom 0.508: IC11.11 180.34,62.23 179.07,63.5 SV22.3
N$324
  Bottom 0.508: IC11.12 178.44,59.69 SV22.4
N$325
  Bottom 0.508: SV22.5 IC11.13
N$326
  Bottom 0.508: IC11.14 178.44,54.61 SV22.6
N$327
  Bottom 0.508: IC11.15 180.34,52.07 179.07,50.8 SV22.7
N$328
  Bottom 0.508: IC11.16 180.97,49.53 179.07,47.63 SV22.8
N$331
  Bottom 0.508: IC12.1 196.85,81.28 198.75,79.38 SV23.2
N$332
  Bottom 0.508: IC12.2 197.49,83.82 198.75,82.55 SV23.3
N$333
  Bottom 0.508: IC12.3 199.39,86.36 SV23.4
N$334
  Bottom 0.508: IC12.4 SV23.5
N$335
  Bottom 0.508: IC12.5 199.39,91.44 SV23.6
N$336
  Bottom 0.508: IC12.6 197.49,93.98 198.75,95.25 SV23.7
N$337
  Bottom 0.508: IC12.7 196.85,96.52 198.75,98.43 SV23.8
N$338
  Bottom 0.508: IC12.8 196.22,99.06 198.75,101.6 SV23.9
N$339
  Bottom 0.508: IC12.9 181.61,99.06 179.07,101.6 SV24.1
N$340
  Bottom 0.508: IC12.10 180.97,96.52 179.07,98.43 SV24.2
N$341
  Bottom 0.508: IC12.11 180.34,93.98 179.07,95.25 SV24.3
N$342
  Bottom 0.508: IC12.12 178.44,91.44 SV24.4
N$343
  Bottom 0.508: SV24.5 IC12.13
N$344
  Bottom 0.508: IC12.14 178.44,86.36 SV24.6
N$345
  Bottom 0.508: IC12.15 180.34,83.82 179.07,82.55 SV24.7
N$346
  Bottom 0.508: IC12.16 180.97,81.28 179.07,79.38 SV24.8
N$349
  Bottom 0.508: IC13.1 196.85,113.03 198.75,111.13 SV25.2
N$350
  Bottom 0.508: IC13.2 197.49,115.57 198.75,114.3 SV25.3
N$351
  Bottom 0.508: IC13.3 199.39,118.11 SV25.4
N$352
  Bottom 0.508: IC13.4 SV25.5
N$353
  Bottom 0.508: IC13.5 199.39,123.19 SV25.6
N$354
  Bottom 0.508: IC13.6 197.49,125.73 198.75,127 SV25.7
N$355
  Bottom 0.508: IC13.7 196.85,128.27 198.75,130.18 SV25.8
N$356
  Bottom 0.508: IC13.8 196.22,130.81 198.75,133.35 SV25.9
N$357
  Bottom 0.508: IC13.9 181.61,130.81 179.07,133.35 SV26.1
N$358
  Bottom 0.508: IC13.10 180.97,128.27 179.07,130.18 SV26.2
N$359
  Bottom 0.508: IC13.11 180.34,125.73 179.07,127 SV26.3
N$360
  Bottom 0.508: IC13.12 178.44,123.19 SV26.4
N$361
  Bottom 0.508: SV26.5 IC13.13
N$362
  Bottom 0.508: IC13.14 178.44,118.11 SV26.6
N$363
  Bottom 0.508: IC13.15 180.34,115.57 179.07,114.3 SV26.7
N$364
  Bottom 0.508: IC13.16 180.97,113.03 179.07,111.13 SV26.8
N$367
  Bottom 0.508: IC14.1 196.85,144.78 198.75,142.88 SV27.2
N$368
  Bottom 0.508: IC14.2 197.49,147.32 198.75,146.05 SV27.3
N$369
  Bottom 0.508: IC14.3 199.39,149.86 SV27.4
N$370
  Bottom 0.508: IC14.4 SV27.5
N$371
  Bottom 0.508: IC14.5 199.39,154.94 SV27.6
N$372
  Bottom 0.508: IC14.6 197.49,157.48 198.75,158.75 SV27.7
N$373
  Bottom 0.508: IC14.7 196.85,160.02 198.75,161.93 SV27.8
N$374
  Bottom 0.508: IC14.8 196.22,162.56 198.75,165.1 SV27.9
N$375
  Bottom 0.508: IC14.9 181.61,162.56 179.07,165.1 SV28.1
N$376
  Bottom 0.508: IC14.10 180.97,160.02 179.07,161.93 SV28.2
N$377
  Bottom 0.508: IC14.11 180.34,157.48 179.07,158.75 SV28.3
N$378
  Bottom 0.508: IC14.12 178.44,154.94 SV28.4
N$379
  Bottom 0.508: SV28.5 IC14.13
N$380
  Bottom 0.508: IC14.14 178.44,149.86 SV28.6
N$381
  Bottom 0.508: IC14.15 180.34,147.32 179.07,146.05 SV28.7
N$382
  Bottom 0.508: IC14.16 180.97,144.78 179.07,142.88 SV28.8
N$385
  Bottom 0.508: IC15.1 196.85,176.53 198.75,174.63 SV29.2
N$386
  Bottom 0.508: IC15.2 197.49,179.07 198.75,177.8 SV29.3
N$387
  Bottom 0.508: IC15.3 199.39,181.61 SV29.4
N$388
  Bottom 0.508: IC15.4 SV29.5
N$389
  Bottom 0.508: IC15.5 199.39,186.69 SV29.6
N$390
  Bottom 0.508: IC15.6 197.49,189.23 198.75,190.5 SV29.7
N$391
  Bottom 0.508: IC15.7 196.85,191.77 198.75,193.68 SV29.8
N$392
  Bottom 0.508: IC15.8 196.22,194.31 198.75,196.85 SV29.9
N$393
  Bottom 0.508: IC15.9 181.61,194.31 179.07,196.85 SV30.1
N$394
  Bottom 0.508: IC15.10 180.97,191.77 179.07,193.68 SV30.2
N$395
  Bottom 0.508: IC15.11 180.34,189.23 179.07,190.5 SV30.3
N$396
  Bottom 0.508: IC15.12 178.44,186.69 SV30.4
N$397
  Bottom 0.508: SV30.5 IC15.13
N$398
  Bottom 0.508: IC15.14 178.44,181.61 SV30.6
N$399
  Bottom 0.508: IC15.15 180.34,179.07 179.07,177.8 SV30.7
N$400
  Bottom 0.508: IC15.16 180.97,176.53 179.07,174.63 SV30.8
N$403
  Bottom 0.508: IC16.1 82.55,49.53 84.45,47.63 SV31.2
N$404
  Bottom 0.508: IC16.2 83.19,52.07 84.45,50.8 SV31.3
N$405
  Bottom 0.508: IC16.3 85.09,54.61 SV31.4
N$406
  Bottom 0.508: IC16.4 SV31.5
N$407
  Bottom 0.508: IC16.5 85.09,59.69 SV31.6
N$408
  Bottom 0.508: IC16.6 83.19,62.23 84.45,63.5 SV31.7
N$409
  Bottom 0.508: IC16.7 82.55,64.77 84.45,66.68 SV31.8
N$410
  Bottom 0.508: IC16.8 81.92,67.31 84.45,69.85 SV31.9
N$411
  Bottom 0.508: IC16.9 67.31,67.31 64.77,69.85 SV32.1
N$412
  Bottom 0.508: IC16.10 66.67,64.77 64.77,66.68 SV32.2
N$413
  Bottom 0.508: IC16.11 66.04,62.23 64.77,63.5 SV32.3
N$414
  Bottom 0.508: IC16.12 64.14,59.69 SV32.4
N$415
  Bottom 0.508: SV32.5 IC16.13
N$416
  Bottom 0.508: IC16.14 64.14,54.61 SV32.6
N$417
  Bottom 0.508: IC16.15 66.04,52.07 64.77,50.8 SV32.7
N$418
  Bottom 0.508: IC16.16 66.67,49.53 64.77,47.63 SV32.8
N$421
  Bottom 0.508: IC17.1 82.55,81.28 84.45,79.38 SV33.2
N$422
  Bottom 0.508: IC17.2 83.19,83.82 84.45,82.55 SV33.3
N$423
  Bottom 0.508: IC17.3 85.09,86.36 SV33.4
N$424
  Bottom 0.508: IC17.4 SV33.5
N$425
  Bottom 0.508: IC17.5 85.09,91.44 SV33.6
N$426
  Bottom 0.508: IC17.6 83.19,93.98 84.45,95.25 SV33.7
N$427
  Bottom 0.508: IC17.7 82.55,96.52 84.45,98.43 SV33.8
N$428
  Bottom 0.508: IC17.8 81.92,99.06 84.45,101.6 SV33.9
N$429
  Bottom 0.508: IC17.9 67.31,99.06 64.77,101.6 SV34.1
N$430
  Bottom 0.508: IC17.10 66.67,96.52 64.77,98.43 SV34.2
N$431
  Bottom 0.508: IC17.11 66.04,93.98 64.77,95.25 SV34.3
N$432
  Bottom 0.508: IC17.12 64.14,91.44 SV34.4
N$433
  Bottom 0.508: SV34.5 IC17.13
N$434
  Bottom 0.508: IC17.14 64.14,86.36 SV34.6
N$435
  Bottom 0.508: IC17.15 66.04,83.82 64.77,82.55 SV34.7
N$436
  Bottom 0.508: IC17.16 66.67,81.28 64.77,79.38 SV34.8
N$439
  Bottom 0.508: IC18.1 82.55,113.03 84.45,111.13 SV35.2
N$440
  Bottom 0.508: IC18.2 83.19,115.57 84.45,114.3 SV35.3
N$441
  Bottom 0.508: IC18.3 85.09,118.11 SV35.4
N$442
  Bottom 0.508: IC18.4 SV35.5
N$443
  Bottom 0.508: IC18.5 85.09,123.19 SV35.6
N$444
  Bottom 0.508: IC18.6 83.19,125.73 84.45,127 SV35.7
N$445
  Bottom 0.508: IC18.7 82.55,128.27 84.45,130.18 SV35.8
N$446
  Bottom 0.508: IC18.8 81.92,130.81 84.45,133.35 SV35.9
N$447
  Bottom 0.508: IC18.9 67.31,130.81 64.77,133.35 SV36.1
N$448
  Bottom 0.508: IC18.10 66.67,128.27 64.77,130.18 SV36.2
N$449
  Bottom 0.508: IC18.11 66.04,125.73 64.77,127 SV36.3
N$450
  Bottom 0.508: IC18.12 64.14,123.19 SV36.4
N$451
  Bottom 0.508: SV36.5 IC18.13
N$452
  Bottom 0.508: IC18.14 64.14,118.11 SV36.6
N$453
  Bottom 0.508: IC18.15 66.04,115.57 64.77,114.3 SV36.7
N$454
  Bottom 0.508: IC18.16 66.67,113.03 64.77,111.13 SV36.8
N$457
  Bottom 0.508: IC19.1 82.55,144.78 84.45,142.88 SV37.2
N$458
  Bottom 0.508: IC19.2 83.19,147.32 84.45,146.05 SV37.3
N$459
  Bottom 0.508: IC19.3 85.09,149.86 SV37.4
N$460
  Bottom 0.508: IC19.4 SV37.5
N$461
  Bottom 0.508: IC19.5 85.09,154.94 SV37.6
N$462
  Bottom 0.508: IC19.6 83.19,157.48 84.45,158.75 SV37.7
N$463
  Bottom 0.508: IC19.7 82.55,160.02 84.45,161.93 SV37.8
N$464
  Bottom 0.508: IC19.8 81.92,162.56 84.45,165.1 SV37.9
N$465
  Bottom 0.508: IC19.9 67.31,162.56 64.77,165.1 SV38.1
N$466
  Bottom 0.508: IC19.10 66.67,160.02 64.77,161.93 SV38.2
N$467
  Bottom 0.508: IC19.11 66.04,157.48 64.77,158.75 SV38.3
N$468
  Bottom 0.508: IC19.12 64.14,154.94 SV38.4
N$469
  Bottom 0.508: SV38.5 IC19.13
N$470
  Bottom 0.508: IC19.14 64.14,149.86 SV38.6
N$471
  Bottom 0.508: IC19.15 66.04,147.32 64.77,146.05 SV38.7
N$472
  Bottom 0.508: IC19.16 66.67,144.78 64.77,142.88 SV38.8
N$475
  Bottom 0.508: IC20.1 83.19,175.9 84.45,174.63 SV39.2
N$476
  Bottom 0.508: IC20.2 85.09,178.44 SV39.3
N$477
  Bottom 0.508: IC20.3 SV39.4
N$478
  Bottom 0.508: IC20.4 85.09,183.52 SV39.5
N$479
  Bottom 0.508: IC20.5 83.19,186.06 84.45,187.33 SV39.6
N$480
  Bottom 0.508: IC20.6 82.55,188.6 84.45,190.5 SV39.7
N$481
  Bottom 0.508: IC20.7 81.92,191.14 84.45,193.68 SV39.8
N$482
  Bottom 0.508: IC20.8 81.28,193.68 84.45,196.85 SV39.9
N$483
  Bottom 0.508: IC20.9 67.94,193.68 64.77,196.85 SV40.1
N$484
  Bottom 0.508: IC20.10 67.31,191.14 64.77,193.68 SV40.2
N$485
  Bottom 0.508: IC20.11 66.67,188.6 64.77,190.5 SV40.3
N$486
  Bottom 0.508: IC20.12 66.04,186.06 64.77,187.33 SV40.4
N$487
  Bottom 0.508: IC20.13 64.14,183.52 SV40.5
N$488
  Bottom 0.508: SV40.6 IC20.14
N$489
  Bottom 0.508: IC20.15 64.14,178.44 SV40.7
N$490
  Bottom 0.508: IC20.16 66.04,175.9 64.77,174.63 SV40.8
N$493
  Bottom 0.508: IC21.1 53.98,49.53 55.88,47.63 SV41.2
N$494
  Bottom 0.508: IC21.2 54.61,52.07 55.88,50.8 SV41.3
N$495
  Bottom 0.508: IC21.3 56.52,54.61 SV41.4
N$496
  Bottom 0.508: IC21.4 SV41.5
N$497
  Bottom 0.508: IC21.5 56.52,59.69 SV41.6
N$498
  Bottom 0.508: IC21.6 54.61,62.23 55.88,63.5 SV41.7
N$499
  Bottom 0.508: IC21.7 53.98,64.77 55.88,66.68 SV41.8
N$500
  Bottom 0.508: IC21.8 53.34,67.31 55.88,69.85 SV41.9
N$501
  Bottom 0.508: IC21.9 38.73,67.31 36.2,69.85 SV42.1
N$502
  Bottom 0.508: IC21.10 38.1,64.77 36.2,66.68 SV42.2
N$503
  Bottom 0.508: IC21.11 37.47,62.23 36.2,63.5 SV42.3
N$504
  Bottom 0.508: IC21.12 35.56,59.69 SV42.4
N$505
  Bottom 0.508: SV42.5 IC21.13
N$506
  Bottom 0.508: IC21.14 35.56,54.61 SV42.6
N$507
  Bottom 0.508: IC21.15 37.47,52.07 36.2,50.8 SV42.7
N$508
  Bottom 0.508: IC21.16 38.1,49.53 36.2,47.63 SV42.8
N$511
  Bottom 0.508: IC22.1 53.98,81.28 55.88,79.38 SV43.2
N$512
  Bottom 0.508: IC22.2 54.61,83.82 55.88,82.55 SV43.3
N$513
  Bottom 0.508: IC22.3 56.52,86.36 SV43.4
N$514
  Bottom 0.508: IC22.4 SV43.5
N$515
  Bottom 0.508: IC22.5 56.52,91.44 SV43.6
N$516
  Bottom 0.508: IC22.6 54.61,93.98 55.88,95.25 SV43.7
N$517
  Bottom 0.508: IC22.7 53.98,96.52 55.88,98.43 SV43.8
N$518
  Bottom 0.508: IC22.8 53.34,99.06 55.88,101.6 SV43.9
N$519
  Bottom 0.508: IC22.9 38.73,99.06 36.2,101.6 SV44.1
N$520
  Bottom 0.508: IC22.10 38.1,96.52 36.2,98.43 SV44.2
N$521
  Bottom 0.508: IC22.11 37.47,93.98 36.2,95.25 SV44.3
N$522
  Bottom 0.508: IC22.12 35.56,91.44 SV44.4
N$523
  Bottom 0.508: SV44.5 IC22.13
N$524
  Bottom 0.508: IC22.14 35.56,86.36 SV44.6
N$525
  Bottom 0.508: IC22.15 37.47,83.82 36.2,82.55 SV44.7
N$526
  Bottom 0.508: IC22.16 38.1,81.28 36.2,79.38 SV44.8
N$529
  Bottom 0.508: IC23.1 53.98,113.03 55.88,111.13 SV45.2
N$530
  Bottom 0.508: IC23.2 54.61,115.57 55.88,114.3 SV45.3
N$531
  Bottom 0.508: IC23.3 56.52,118.11 SV45.4
N$532
  Bottom 0.508: IC23.4 SV45.5
N$533
  Bottom 0.508: IC23.5 56.52,123.19 SV45.6
N$534
  Bottom 0.508: IC23.6 54.61,125.73 55.88,127 SV45.7
N$535
  Bottom 0.508: IC23.7 53.98,128.27 55.88,130.18 SV45.8
N$536
  Bottom 0.508: IC23.8 53.34,130.81 55.88,133.35 SV45.9
N$537
  Bottom 0.508: IC23.9 38.73,130.81 36.2,133.35 SV46.1
N$538
  Bottom 0.508: IC23.10 38.1,128.27 36.2,130.18 SV46.2
N$539
  Bottom 0.508: IC23.11 37.47,125.73 36.2,127 SV46.3
N$540
  Bottom 0.508: IC23.12 35.56,123.19 SV46.4
N$541
  Bottom 0.508: SV46.5 IC23.13
N$542
  Bottom 0.508: IC23.14 35.56,118.11 SV46.6
N$543
  Bottom 0.508: IC23.15 37.47,115.57 36.2,114.3 SV46.7
N$544
  Bottom 0.508: IC23.16 38.1,113.03 36.2,111.13 SV46.8
N$547
  Bottom 0.508: IC24.1 53.98,144.78 55.88,142.88 SV47.2
N$548
  Bottom 0.508: IC24.2 54.61,147.32 55.88,146.05 SV47.3
N$549
  Bottom 0.508: IC24.3 56.52,149.86 SV47.4
N$550
  Bottom 0.508: IC24.4 SV47.5
N$551
  Bottom 0.508: IC24.5 56.52,154.94 SV47.6
N$552
  Bottom 0.508: IC24.6 54.61,157.48 55.88,158.75 SV47.7
N$553
  Bottom 0.508: IC24.7 53.98,160.02 55.88,161.93 SV47.8
N$554
  Bottom 0.508: IC24.8 53.34,162.56 55.88,165.1 SV47.9
N$555
  Bottom 0.508: IC24.9 38.73,162.56 36.2,165.1 SV48.1
N$556
  Bottom 0.508: IC24.10 38.1,160.02 36.2,161.93 SV48.2
N$557
  Bottom 0.508: IC24.11 37.47,157.48 36.2,158.75 SV48.3
N$558
  Bottom 0.508: IC24.12 35.56,154.94 SV48.4
N$559
  Bottom 0.508: SV48.5 IC24.13
N$560
  Bottom 0.508: IC24.14 35.56,149.86 SV48.6
N$561
  Bottom 0.508: IC24.15 37.47,147.32 36.2,146.05 SV48.7
N$562
  Bottom 0.508: IC24.16 38.1,144.78 36.2,142.88 SV48.8
N$565
  Bottom 0.508: IC25.1 53.98,176.53 55.88,174.63 SV49.2
N$566
  Bottom 0.508: IC25.2 54.61,179.07 55.88,177.8 SV49.3
N$567
  Bottom 0.508: IC25.3 56.52,181.61 SV49.4
N$568
  Bottom 0.508: IC25.4 SV49.5
N$569
  Bottom 0.508: IC25.5 56.52,186.69 SV49.6
N$570
  Bottom 0.508: IC25.6 54.61,189.23 55.88,190.5 SV49.7
N$571
  Bottom 0.508: IC25.7 53.98,191.77 55.88,193.68 SV49.8
N$572
  Bottom 0.508: IC25.8 53.34,194.31 55.88,196.85 SV49.9
N$573
  Bottom 0.508: IC25.9 38.73,194.31 36.2,196.85 SV50.1
N$574
  Bottom 0.508: IC25.10 38.1,191.77 36.2,193.68 SV50.2
N$575
  Bottom 0.508: IC25.11 37.47,189.23 36.2,190.5 SV50.3
N$576
  Bottom 0.508: IC25.12 35.56,186.69 SV50.4
N$577
  Bottom 0.508: SV50.5 IC25.13
N$578
  Bottom 0.508: IC25.14 35.56,181.61 SV50.6
N$579
  Bottom 0.508: IC25.15 37.47,179.07 36.2,177.8 SV50.7
N$580
  Bottom 0.508: IC25.16 38.1,176.53 36.2,174.63 SV50.8
N$583
  Bottom 0.508: IC26.1 25.4,49.53 27.3,47.63 SV51.2
N$584
  Bottom 0.508: IC26.2 26.04,52.07 27.3,50.8 SV51.3
N$585
  Bottom 0.508: IC26.3 27.94,54.61 SV51.4
N$586
  Bottom 0.508: IC26.4 SV51.5
N$587
  Bottom 0.508: IC26.5 27.94,59.69 SV51.6
N$588
  Bottom 0.508: IC26.6 26.04,62.23 27.3,63.5 SV51.7
N$589
  Bottom 0.508: IC26.7 25.4,64.77 27.3,66.68 SV51.8
N$590
  Bottom 0.508: IC26.8 24.77,67.31 27.3,69.85 SV51.9
N$591
  Bottom 0.508: IC26.9 10.16,67.31 7.62,69.85 SV52.1
N$592
  Bottom 0.508: IC26.10 9.53,64.77 7.62,66.68 SV52.2
N$593
  Bottom 0.508: IC26.11 8.89,62.23 7.62,63.5 SV52.3
N$594
  Bottom 0.508: IC26.12 6.99,59.69 SV52.4
N$595
  Bottom 0.508: SV52.5 IC26.13
N$596
  Bottom 0.508: IC26.14 6.99,54.61 SV52.6
N$597
  Bottom 0.508: IC26.15 8.89,52.07 7.62,50.8 SV52.7
N$598
  Bottom 0.508: IC26.16 9.53,49.53 7.62,47.63 SV52.8
N$601
  Bottom 0.508: IC27.1 25.4,81.28 27.3,79.38 SV53.2
N$602
  Bottom 0.508: IC27.2 26.04,83.82 27.3,82.55 SV53.3
N$603
  Bottom 0.508: IC27.3 27.94,86.36 SV53.4
N$604
  Bottom 0.508: IC27.4 SV53.5
N$605
  Bottom 0.508: IC27.5 27.94,91.44 SV53.6
N$606
  Bottom 0.508: IC27.6 26.04,93.98 27.3,95.25 SV53.7
N$607
  Bottom 0.508: IC27.7 25.4,96.52 27.3,98.43 SV53.8
N$608
  Bottom 0.508: IC27.8 24.77,99.06 27.3,101.6 SV53.9
N$609
  Bottom 0.508: IC27.9 10.16,99.06 7.62,101.6 SV54.1
N$610
  Bottom 0.508: IC27.10 9.53,96.52 7.62,98.43 SV54.2
N$611
  Bottom 0.508: IC27.11 8.89,93.98 7.62,95.25 SV54.3
N$612
  Bottom 0.508: IC27.12 6.99,91.44 SV54.4
N$613
  Bottom 0.508: SV54.5 IC27.13
N$614
  Bottom 0.508: IC27.14 6.99,86.36 SV54.6
N$615
  Bottom 0.508: IC27.15 8.89,83.82 7.62,82.55 SV54.7
N$616
  Bottom 0.508: IC27.16 9.53,81.28 7.62,79.38 SV54.8
N$619
  Bottom 0.508: IC28.1 25.4,113.03 27.3,111.13 SV55.2
N$620
  Bottom 0.508: IC28.2 26.04,115.57 27.3,114.3 SV55.3
N$621
  Bottom 0.508: IC28.3 27.94,118.11 SV55.4
N$622
  Bottom 0.508: IC28.4 SV55.5
N$623
  Bottom 0.508: IC28.5 27.94,123.19 SV55.6
N$624
  Bottom 0.508: IC28.6 26.04,125.73 27.3,127 SV55.7
N$625
  Bottom 0.508: IC28.7 25.4,128.27 27.3,130.18 SV55.8
N$626
  Bottom 0.508: IC28.8 24.77,130.81 27.3,133.35 SV55.9
N$627
  Bottom 0.508: IC28.9 10.16,130.81 7.62,133.35 SV56.1
N$628
  Bottom 0.508: IC28.10 9.53,128.27 7.62,130.18 SV56.2
N$629
  Bottom 0.508: IC28.11 8.89,125.73 7.62,127 SV56.3
N$630
  Bottom 0.508: IC28.12 6.99,123.19 SV56.4
N$631
  Bottom 0.508: SV56.5 IC28.13
N$632
  Bottom 0.508: IC28.14 6.99,118.11 SV56.6
N$633
  Bottom 0.508: IC28.15 8.89,115.57 7.62,114.3 SV56.7
N$634
  Bottom 0.508: IC28.16 9.53,113.03 7.62,111.13 SV56.8
N$637
  Bottom 0.508: IC29.1 25.4,144.78 27.3,142.88 SV57.2
N$638
  Bottom 0.508: IC29.2 26.04,147.32 27.3,146.05 SV57.3
N$639
  Bottom 0.508: IC29.3 27.94,149.86 SV57.4
N$640
  Bottom 0.508: IC29.4 SV57.5
N$641
  Bottom 0.508: IC29.5 27.94,154.94 SV57.6
N$642
  Bottom 0.508: IC29.6 26.04,157.48 27.3,158.75 SV57.7
N$643
  Bottom 0.508: IC29.7 25.4,160.02 27.3,161.93 SV57.8
N$644
  Bottom 0.508: IC29.8 24.77,162.56 27.3,165.1 SV57.9
N$645
  Bottom 0.508: IC29.9 10.16,162.56 7.62,165.1 SV58.1
N$646
  Bottom 0.508: IC29.10 9.53,160.02 7.62,161.93 SV58.2
N$647
  Bottom 0.508: IC29.11 8.89,157.48 7.62,158.75 SV58.3
N$648
  Bottom 0.508: IC29.12 6.99,154.94 SV58.4
N$649
  Bottom 0.508: SV58.5 IC29.13
N$650
  Bottom 0.508: IC29.14 6.99,149.86 SV58.6
N$651
  Bottom 0.508: IC29.15 8.89,147.32 7.62,146.05 SV58.7
N$652
  Bottom 0.508: IC29.16 9.53,144.78 7.62,142.88 SV58.8
N$655
  Bottom 0.508: IC30.1 25.4,176.53 27.3,174.63 SV59.2
N$656
  Bottom 0.508: IC30.2 26.04,179.07 27.3,177.8 SV59.3
N$657
  Bottom 0.508: IC30.3 27.94,181.61 SV59.4
N$658
  Bottom 0.508: IC30.4 SV59.5
N$659
  Bottom 0.508: IC30.5 27.94,186.69 SV59.6
N$660
  Bottom 0.508: IC30.6 26.04,189.23 27.3,190.5 SV59.7
N$661
  Bottom 0.508: IC30.7 25.4,191.77 27.3,193.68 SV59.8
N$662
  Bottom 0.508: IC30.8 24.77,194.31 27.3,196.85 SV59.9
N$663
  Bottom 0.508: IC30.9 10.16,194.31 7.62,196.85 SV60.1
N$664
  Bottom 0.508: IC30.10 9.53,191.77 7.62,193.68 SV60.2
N$665
  Bottom 0.508: IC30.11 8.89,189.23 7.62,190.5 SV60.3
N$666
  Bottom 0.508: IC30.12 6.99,186.69 SV60.4
N$667
  Bottom 0.508: SV60.5 IC30.13
N$668
  Bottom 0.508: IC30.14 6.99,181.61 SV60.6
N$669
  Bottom 0.508: IC30.15 8.89,179.07 7.62,177.8 SV60.7
N$670
  Bottom 0.508: IC30.16 9.53,176.53 7.62,174.63 SV60.8
N$673
  Bottom 0.508: SV61.2 136.53,48.9 140.34,52.71 IC31.1 IC39.1
N$674
  Bottom 0.508: SV61.3 139.7,49.53 142.88,52.71 IC31.2 IC39.2
N$675
  Bottom 0.508: SV61.4 142.88,48.9 145.41,51.44 IC31.3 IC39.3
N$676
  Bottom 0.508: SV61.5 146.05,48.9 147.96,50.8 IC31.4 IC39.4
N$677
  Bottom 0.508: SV61.6 149.22,48.9 150.5,50.17 IC31.5 IC39.5
N$678
  Bottom 0.508: SV61.7 153.03,48.26 IC31.6 IC39.6
N$679
  Bottom 0.508: SV61.8 IC31.7 IC39.7
N$680
  Bottom 0.508: SV61.9 158.12,48.26 IC31.8 IC39.8
N$681
  Bottom 0.508: SV61.10 161.93,48.9 160.66,50.17 IC31.9 IC39.9
N$682
  Bottom 0.508: SV61.11 165.1,48.9 163.19,50.8 IC31.10 IC39.10
N$683
  Bottom 0.508: SV61.12 168.28,48.9 165.74,51.44 IC31.11 IC39.11
N$684
  Bottom 0.508: SV61.13 171.45,49.53 168.28,52.71 IC31.12 IC39.12
N$685
  Bottom 0.508: SV62.1 171.45,74.93 168.28,71.76 IC31.13 IC39.13
N$686
  Bottom 0.508: SV62.2 168.28,74.93 165.74,72.39 IC31.14 IC39.14
N$687
  Bottom 0.508: SV62.3 165.1,74.93 163.19,73.03 IC31.15 IC39.15
N$688
  Bottom 0.508: SV62.4 161.93,74.93 160.66,73.66 IC31.16 IC39.16
N$689
  Bottom 0.508: SV62.5 158.12,75.57 IC31.17 IC39.17
N$690
  Bottom 0.508: SV62.6 IC31.18 IC39.18
N$691
  Bottom 0.508: SV62.7 153.03,75.57 IC31.19 IC39.19
N$692
  Bottom 0.508: SV62.8 149.22,74.93 150.5,73.66 IC31.20 IC39.20
N$693
  Bottom 0.508: SV62.9 146.05,74.93 147.96,73.03 IC31.21 IC39.21
N$694
  Bottom 0.508: SV62.10 142.88,74.93 145.41,72.39 IC31.22 IC39.22
N$695
  Bottom 0.508: SV62.11 139.7,74.93 142.88,71.76 IC31.23 IC39.23
N$696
